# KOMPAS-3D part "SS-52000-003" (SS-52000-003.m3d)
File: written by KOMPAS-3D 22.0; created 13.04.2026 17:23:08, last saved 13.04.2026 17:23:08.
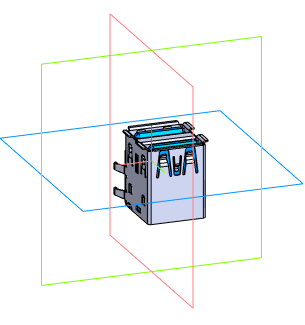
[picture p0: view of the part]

Document properties: Автор: Andrey; Полное имя файла: C:\Users\User1\Documents\SS-52000-003.m3d

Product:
- Part/product: SS-52000-003

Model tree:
1. Операция без истории:1
2. Операция без истории:2
3. Операция без истории:3
4. Операция без истории:4
5. Операция без истории:5
6. Операция без истории:6
7. Операция без истории:7
8. Операция без истории:8
9. Операция без истории:9
10. Операция без истории:10
11. Операция без истории:11
12. Операция без истории:12
13. Операция без истории:13
14. Операция без истории:14
15. Операция без истории:15
16. Операция без истории:16
17. Операция без истории:17
18. Операция без истории:18
19. Операция без истории:19
20. Операция без истории:20
21. Операция без истории:21
22. Операция без истории:22

Expressions: SS-52000-003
